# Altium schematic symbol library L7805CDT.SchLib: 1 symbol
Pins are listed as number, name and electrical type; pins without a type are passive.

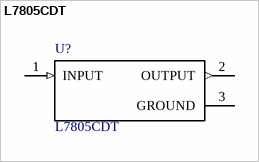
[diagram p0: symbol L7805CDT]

## L7805CDT
designator U?
Linear Voltage Regulator IC Positive Fixed 1 Output  1.5A DPAK; MF: STMicroelectronics
footprint *VREG_L7805CDT
pins: 1 INPUT (in), 2 OUTPUT (out), 3 GROUND (power)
